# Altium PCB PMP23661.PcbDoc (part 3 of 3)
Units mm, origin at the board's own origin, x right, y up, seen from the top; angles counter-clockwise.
Board outline 209 x 127 mm, 4 copper layers (Top Layer, Layer 1, Layer 2, Bottom Layer), stack 1.787 mm thick; 235 components, 114 nets, 814 pads, 405 vias.
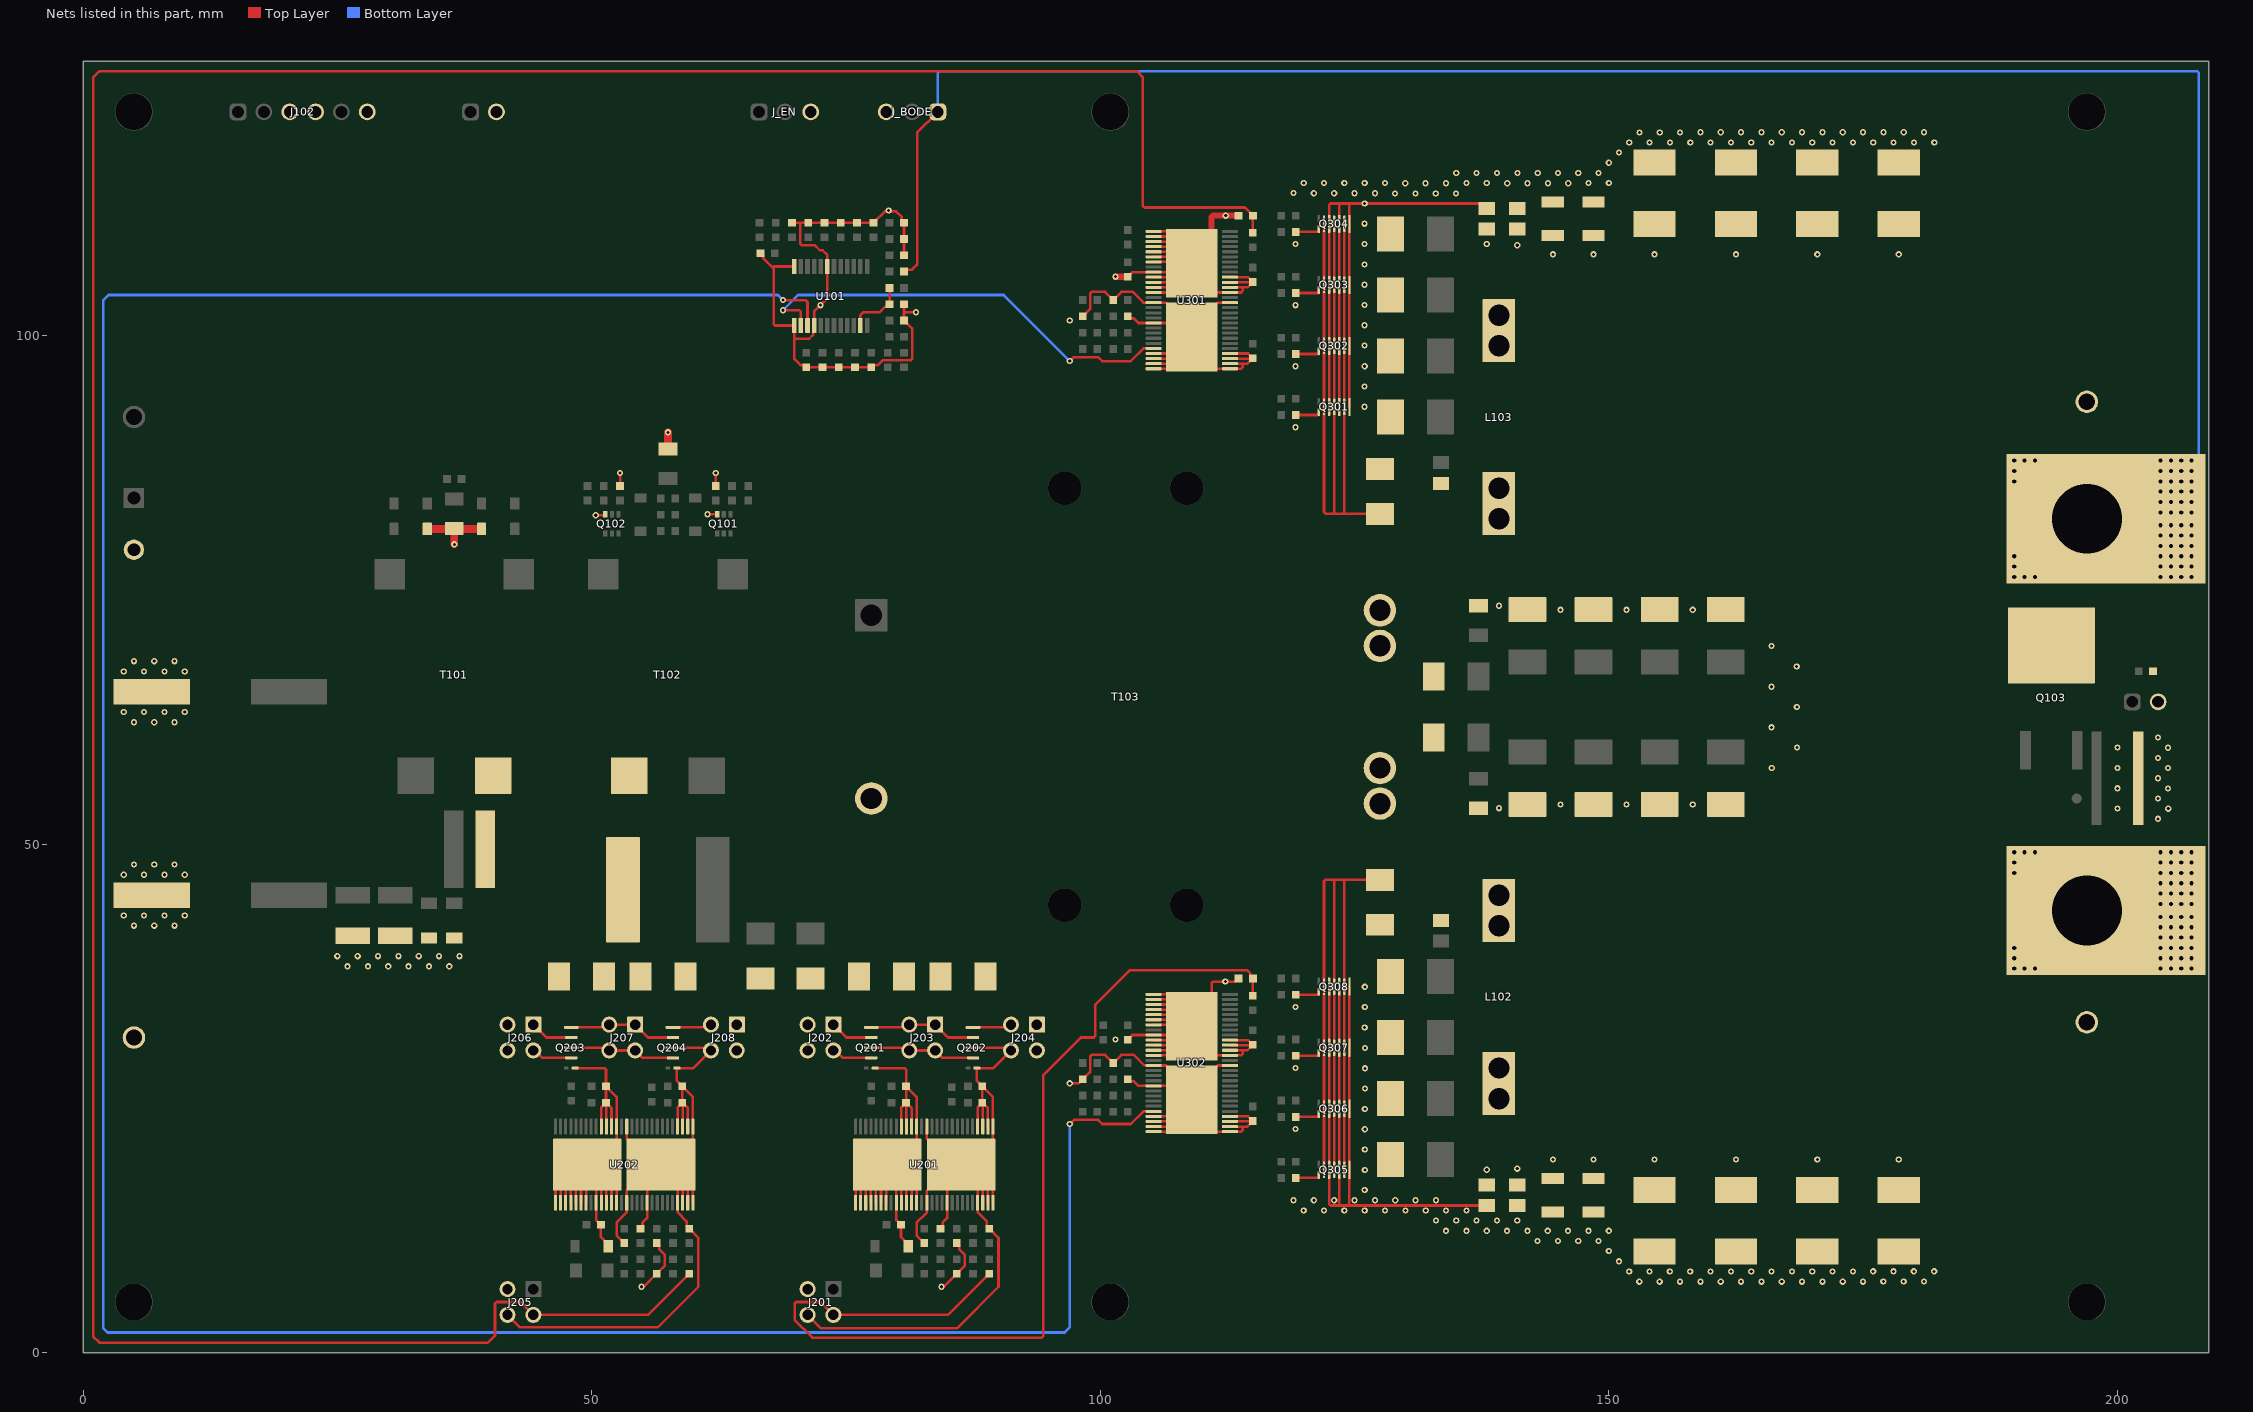
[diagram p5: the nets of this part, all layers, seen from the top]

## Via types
v1: diameter 0.61, hole 0.305, Top Layer to Bottom Layer, 289 vias
v2: diameter 0.813, hole 0.406, Top Layer to Bottom Layer, 116 vias

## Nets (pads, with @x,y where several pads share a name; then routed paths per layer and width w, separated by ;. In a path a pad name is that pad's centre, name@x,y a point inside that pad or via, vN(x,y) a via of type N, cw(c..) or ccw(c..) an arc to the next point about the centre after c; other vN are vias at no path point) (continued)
PGND: C101.2 C102.2 C103.2 C105.2 C107.2 C108.2 C201.2 C202.2 C203.1 C206.1 C207.1 C208.2 C209.1 C212.1 C303.1 C304.1 C310.1 C311.1 D106.2 D108.2 D111.2 J101.2 J102.3 J102.4 J102.6 J201.2 J201.4 J204.1 J204.2 J204.3 J204.4 J205.2 J205.4 J208.1 J208.2 J208.3 J208.4 Q202.2 Q202.4 Q202.6 Q204.2 Q204.4 Q204.6 R205.2 R206.2 R211.2 R216.2 R217.2 R222.2 R313.2 R338.2 TP102.1 U201.15 U201.19 U201.25 U201.26 U201.27 U201.28 U201.29 U201.30 U201.31 U201.32 U201.42 U201.58 U202.15 U202.19 U202.25 U202.26 U202.27 U202.28 U202.29 U202.30 U202.31 U202.32 U202.42 U202.58 U301.1 U301.2 U301.3 U301.4 U301.5 U301.6 U301.7 U301.9 U301.10 U301.11 U301.12 U301.13 U301.44 U301.45 U301.46 U301.47 U301.57 U302.1 U302.2 U302.3 U302.4 U302.5 U302.6 U302.7 U302.9 U302.10 U302.11 U302.12 U302.13 U302.44 U302.45 U302.46 U302.47 U302.57 | length 277
  Top Layer w0.254: J205.4@41.73,3.73 42.96,2.5 56.5,2.5 60.5,6.5 60.5,11.311 C207.1@59.6,12.211 59.346,12.465 59.346,12.936 58.455,13.828 58.455,14.745 U202.25@58.45,14.75 58.45,16.077 57.977,16.55 U202.58@57.6,16.55 ; J205.2@41.73,6.27 J205.2@41.982,6.018 ; C209.1@53.2,10.789 52.45,11.539 52.45,12.804 53.45,13.804 U202.15@53.45,14.75 53.45,15.95 54.05,16.55 U202.58@54.3,16.55 ; U202.42@53.45,22.25 53.45,21.05 54.05,20.45 U202.58@54.3,20.45 ; C208.2@54.8,12.211 55.002,12.413 55.002,12.802 55.45,13.25 U202.19@55.45,14.75 55.45,16.5 U202.58@55.4,16.55 ; v1(54.9,6.5) 54.968,6.568 55.179,6.568 R216.2@56.4,7.789 57.2,8.589 57.2,9.636 56.654,10.182 56.654,10.535 R217.2@56.4,10.789 ; Q204.4@58,30 61.104,30 61.374,29.73 J208.4@61.73,29.73 60,28 Q204.2@58.375,28 58.375,26.736 R222.2@58.911,26.2 ; Q204.6@58,32 61.104,32 61.374,32.27 J208.2@61.73,32.27 ; U202.32@58.45,22.25 58.45,24.139 C212.1@58.911,24.6 ; U202.58@58.7,16.55 58.95,16.3 U202.26@58.95,14.75 ; U202.58@58.7,17.85 59.45,17.1 U202.27@59.45,14.75 ; U202.31@58.95,22.25 58.95,24.561 C212.1@58.911,24.6 ; U202.30@59.45,22.25 59.45,24.061 C212.1@58.911,24.6 ; U202.58@59.8,16.55 59.95,16.4 U202.28@59.95,14.75 ; U202.58@59.8,20.45 59.95,20.6 U202.29@59.95,22.25 59.95,25.161 R222.2@58.911,26.2 ; J201.4@71.23,3.73 72.56,2.4 85.9,2.4 90,6.5 90,11.311 ; C203.1@82.7,10.789 81.95,11.539 81.95,12.804 82.95,13.804 U201.15@82.95,14.75 82.95,15.95 83.55,16.55 U201.58@83.8,16.55 ; U201.42@82.95,22.25 82.95,21.05 83.55,20.45 U201.58@83.8,20.45 ; C202.2@84.3,12.211 84.502,12.413 84.502,12.802 84.95,13.25 U201.19@84.95,14.75 84.95,16.5 U201.58@84.9,16.55 ; v1(84.4,6.5) 84.468,6.568 84.679,6.568 R205.2@85.9,7.789 86.7,8.589 86.7,9.636 86.154,10.182 86.154,10.535 R206.2@85.9,10.789 ; U201.58@87.1,16.55 87.477,16.55 87.95,16.077 U201.25@87.95,14.75 87.955,14.745 87.955,13.828 88.846,12.936 88.846,12.465 C201.2@89.1,12.211 ; Q202.4@87.5,30 90.604,30 90.874,29.73 J204.4@91.23,29.73 89.5,28 Q202.2@87.875,28 87.875,26.736 R211.2@88.411,26.2 ; Q202.6@87.5,32 90.604,32 90.874,32.27 J204.2@91.23,32.27 ; U201.32@87.95,22.25 87.95,24.139 C206.1@88.411,24.6 ; U201.58@88.2,16.55 88.45,16.3 U201.26@88.45,14.75 ; U201.58@88.2,17.85 88.95,17.1 U201.27@88.95,14.75 ; U201.31@88.45,22.25 88.45,24.561 C206.1@88.411,24.6 ; U201.30@88.95,22.25 88.95,24.061 C206.1@88.411,24.6 ; U201.58@89.3,16.55 89.45,16.4 U201.28@89.45,14.75 ; U201.58@89.3,20.45 89.45,20.6 U201.29@89.45,22.25 89.45,25.161 R211.2@88.411,26.2 ; C310.1@102.7,30.789 103.161,31.25 U302.9@105.25,31.25 107.8,31.25 108.35,31.8 107.9,32.25 U302.7@105.25,32.25 ; C303.1@102.7,105.789 103.161,106.25 U301.9@105.25,106.25 107.8,106.25 108.35,106.8 107.9,107.25 U301.7@105.25,107.25 ; U302.13@105.25,29.25 108,29.25 U302.57@108.35,29.6 ; U302.12@105.25,29.75 U302.57@107.05,29.75 ; U302.11@105.25,30.25 U302.57@107.7,30.25 ; U302.10@105.25,30.75 U302.57@107.05,30.75 ; U302.6@105.25,32.75 U302.57@107.05,32.75 ; U302.5@105.25,33.25 107.6,33.25 107.975,33.625 107.85,33.75 U302.4@105.25,33.75 ; U302.3@105.25,34.25 108.1,34.25 107.6,34.75 U302.2@105.25,34.75 ; U302.1@105.25,35.25 U302.57@107.05,35.25 ; U301.13@105.25,104.25 108,104.25 U301.57@108.35,104.6 ; U301.12@105.25,104.75 U301.57@107.05,104.75 ; U301.11@105.25,105.25 U301.57@107.7,105.25 ; U301.10@105.25,105.75 U301.57@107.05,105.75 ; U301.6@105.25,107.75 U301.57@107.05,107.75 ; U301.5@105.25,108.25 107.6,108.25 107.975,108.625 107.85,108.75 U301.4@105.25,108.75 ; U301.3@105.25,109.25 108.1,109.25 107.6,109.75 U301.2@105.25,109.75 ; U301.1@105.25,110.25 U301.57@107.05,110.25 ; U302.57@110.95,29.6 111.3,29.25 U302.44@112.75,29.25 113.851,29.25 114,29.399 114,29.75 ; U302.57@110.95,35.1 110.95,36.351 111.099,36.5 113.186,36.5 113.232,36.546 113.335,36.546 R338.2@113.589,36.8 ; U301.57@110.95,104.6 111.3,104.25 U301.44@112.75,104.25 113.851,104.25 114,104.399 114,104.75 ; U302.45@112.75,29.75 114,29.75 ; U302.46@112.75,30.25 114.961,30.25 C311.1@115,30.289 ; U302.47@112.75,30.75 114.539,30.75 C311.1@115,30.289 ; U301.45@112.75,104.75 114,104.75 ; U301.46@112.75,105.25 114.961,105.25 C304.1@115,105.289 ; U301.47@112.75,105.75 114.539,105.75 C304.1@115,105.289 ; C212.1@58.911,24.6 R222.2@58.911,26.2 ; C206.1@88.411,24.6 R211.2@88.411,26.2 ; C201.2@89.1,12.211 90,11.311 ; C201.2@89.1,12.211 90,11.311 ; 114,29.75 114.461,29.75 C311.1@115,30.289 ; 114,104.75 114.461,104.75 C304.1@115,105.289
  Top Layer w0.6: v1(101.5,105.8) 101.502,105.798 102.691,105.798 C303.1@102.7,105.789 ; U301.57@110.95,110.1 110.95,111.651 111.099,111.8 v1(112.344,111.8) R313.2@113.589,111.8
  other v1: 101.5,30.8 112.3,36.5 26,38 28,38 30,38 32,38 34,38 36,38 25,39 27,39 29,39 31,39 33,39 35,39 37,39 5,42 7,42 9,42 4,43 6,43 8,43 10,43 4,47 6,47 8,47 10,47 5,48 7,48 9,48 5,62 7,62 9,62 4,63 6,63 8,63 10,63 4,67 6,67 8,67 10,67 5,68 7,68 9,68
PRIswA: C210.1 C211.1 D105.2 D106.1 D204.2 J207.1 J207.2 J207.3 J207.4 L101.1 Q203.2 Q203.4 Q203.6 Q204.3 Q204.5 R221.2 T102.1 U202.1 U202.2 U202.3 U202.4 U202.5 U202.6 U202.7 U202.9 U202.10 U202.11 U202.12 U202.13 U202.44 U202.45 U202.46 U202.47 U202.57 | length 80.7
  Top Layer w0.254: U202.1@46.45,14.75 46.45,16.4 U202.57@46.6,16.55 ; U202.2@46.95,14.75 U202.57@46.95,17.5 ; U202.3@47.45,14.75 47.45,17.6 U202.57@47.7,17.85 ; U202.4@47.95,14.75 U202.57@47.95,17.6 ; Q203.4@48,30 J207.4@51.73,30 ; Q203.6@48,32 52,32 J207.2@51.73,32.27 J207.1@54.27,32.27 55.54,31 Q204.5@58,31 ; Q203.2@48.375,28 51.262,28 51.411,27.851 R221.2@51.411,26.2 ; U202.5@48.45,14.75 48.45,17.5 U202.57@48.8,17.85 ; U202.57@48.8,16.55 48.95,16.4 U202.6@48.95,14.75 ; U202.7@49.45,14.75 49.45,18.375 U202.57@49.575,18.5 ; U202.10@50.95,14.75 U202.57@50.95,16.55 ; U202.47@50.95,22.25 50.95,24.139 C211.1@51.411,24.6 ; U202.57@51,17.85 50.45,17.3 U202.9@50.45,14.75 50.45,13.061 C210.1@50.911,12.6 50.911,11.379 51.637,10.653 D204.2@51.637,10.5 ; U202.57@51,19.15 51.45,18.7 U202.11@51.45,14.75 ; U202.46@51.45,22.25 C211.1@51.45,24.561 ; J207.4@51.73,29.73 J207.3@54.27,29.73 55,29 Q204.3@58,29 ; U202.12@51.95,14.75 U202.57@51.95,16.55 ; U202.45@51.95,22.25 51.95,24.061 C211.1@51.411,24.6 ; U202.57@52.1,17.85 52.45,17.5 U202.13@52.45,14.75 ; U202.57@52.1,20.45 52.45,20.8 U202.44@52.45,22.25 52.45,25.161 R221.2@51.411,26.2 ; C211.1@51.411,24.6 R221.2@51.411,26.2
PRIswB: C204.1 C205.1 D107.2 D108.1 D202.2 J203.1 J203.2 J203.3 J203.4 Q201.2 Q201.4 Q201.6 Q202.3 Q202.5 R210.2 T103.2 U201.1 U201.2 U201.3 U201.4 U201.5 U201.6 U201.7 U201.9 U201.10 U201.11 U201.12 U201.13 U201.44 U201.45 U201.46 U201.47 U201.57 | length 80.7
  Top Layer w0.254: U201.1@75.95,14.75 75.95,16.4 U201.57@76.1,16.55 ; U201.2@76.45,14.75 U201.57@76.45,17.5 ; U201.3@76.95,14.75 76.95,17.6 U201.57@77.2,17.85 ; U201.4@77.45,14.75 U201.57@77.45,17.6 ; Q201.4@77.5,30 J203.4@81.23,30 ; Q201.6@77.5,32 81.5,32 J203.2@81.23,32.27 J203.1@83.77,32.27 85.04,31 Q202.5@87.5,31 ; Q201.2@77.875,28 80.762,28 80.911,27.851 R210.2@80.911,26.2 ; U201.5@77.95,14.75 77.95,17.5 U201.57@78.3,17.85 ; U201.57@78.3,16.55 78.45,16.4 U201.6@78.45,14.75 ; U201.7@78.95,14.75 78.95,18.375 U201.57@79.075,18.5 ; U201.10@80.45,14.75 U201.57@80.45,16.55 ; U201.47@80.45,22.25 80.45,24.139 C205.1@80.911,24.6 ; U201.57@80.5,17.85 79.95,17.3 U201.9@79.95,14.75 79.95,13.061 C204.1@80.411,12.6 80.411,11.379 81.137,10.652 D202.2@81.137,10.5 ; U201.57@80.5,19.15 80.95,18.7 U201.11@80.95,14.75 ; U201.46@80.95,22.25 80.95,24.561 C205.1@80.911,24.6 ; J203.4@81.23,29.73 J203.3@83.77,29.73 84.5,29 Q202.3@87.5,29 ; U201.12@81.45,14.75 U201.57@81.45,16.55 ; U201.45@81.45,22.25 81.45,24.061 C205.1@80.911,24.6 ; U201.57@81.6,17.85 81.95,17.5 U201.13@81.95,14.75 ; U201.57@81.6,20.45 81.95,20.8 U201.44@81.95,22.25 81.95,25.161 R210.2@80.911,26.2 ; C205.1@80.911,24.6 R210.2@80.911,26.2
PWMA: J205.3 R212.2 R312.1 R313.1 | length 317.6
  Top Layer w0.254: R212.2@59.6,7.789 55.541,3.73 J205.3@44.27,3.73 43,5 40.649,5 40.5,4.851 40.5,1.7 39.8,1 1.6,1 1,1.6 1,125.4 1.6,126 103.6,126 104.2,125.4 104.2,112.749 104.349,112.6 114.211,112.6 114.757,112.054 R313.1@115.011,111.8 115,111.789 R312.1@115,110.111
PWMB: J201.3 R201.2 R337.1 R338.1 | length 102.7
  Top Layer w0.254: R201.2@89.1,7.789 85.041,3.73 J201.3@73.77,3.73 72.5,5 70.109,5 69.96,4.851 69.96,3.24 71.7,1.5 94.251,1.5 94.4,1.649 94.4,27.3 98.1,31 99.351,31 99.5,31.149 99.5,34.211 102.889,37.6 114.469,37.6 114.757,37.312 114.757,37.054 R338.1@115.011,36.8 115,36.789 R337.1@115,35.111
SECswA: C314.1 D113.1 D302.2 L102.1 Q305.3 Q305.5 Q305.7 Q306.3 Q306.5 Q306.7 Q307.3 Q307.5 Q307.7 Q308.3 Q308.5 Q308.7 T103.3 | length 90.9
  Top Layer w0.254: Q305.3@122,18 Q306.3@122,24 Q307.3@122,30 Q308.3@122,36 122,46.361 122.149,46.51 123,46.51 ; Q305.5@123,18 Q306.5@123,24 Q307.5@123,30 Q308.5@123,36 123,46.51 ; Q305.7@124,18 124,46.51 ; D113.1@127.5,46.51 124,46.51 ; 123,46.51 124,46.51
SECswB: C307.1 D114.1 D301.2 L103.2 Q301.3 Q301.5 Q301.7 Q302.3 Q302.5 Q302.7 Q303.3 Q303.5 Q303.7 Q304.3 Q304.5 Q304.7 T103.4 | length 90.9
  Top Layer w0.254: Q304.3@122,111 Q303.3@122,105 Q302.3@122,99 Q301.3@122,93 122,82.69 122.2,82.49 123,82.49 ; Q304.5@123,111 Q303.5@123,105 Q302.5@123,99 Q301.5@123,93 123,82.49 ; Q304.7@124,111 Q303.7@124,105 Q302.7@124,99 Q301.7@124,93 124,82.49 ; D114.1@127.5,82.49 124,82.49 ; 123,82.49 124,82.49
SGND: C104.2 C106.1 C109.1 C110.2 C111.1 C112.2 C113.2 C114.2 C115.2 C116.2 C117.2 C118.2 C119.2 C120.2 C121.2 C122.2 C123.2 C124.2 C125.2 C126.2 C127.2 C128.2 C129.2 C130.2 C301.2 C302.1 C306.1 C308.2 C309.1 C313.1 D102.2 D104.2 D113.2 D114.2 J103.2 J105.1 J106.2 J_BODE.3 J_EN.3 Q101.3 Q102.3 Q301.2 Q301.4 Q301.6 Q301.8 Q302.2 Q302.4 Q302.6 Q302.8 Q303.2 Q303.4 Q303.6 Q303.8 Q304.2 Q304.4 Q304.6 Q304.8 Q305.2 Q305.4 Q305.6 Q305.8 Q306.2 Q306.4 Q306.6 Q306.8 Q307.2 Q307.4 Q307.6 Q307.8 Q308.2 Q308.4 Q308.6 Q308.8 R103.2 R104.1 R107.2 R108.1 R111.1 R112.1 R113.1 R117.1 R120.1 R121.1 R122.1 R124.2 R129.1 R130.1 R131.1 R303.2 R314.1 R319.1 R320.2 R321.2 R322.2 R323.2 R324.1 R325.1 R328.2 R339.1 R344.1 R345.2 R346.2 R347.2 R348.2 R349.1 R350.1 TP105.1 U101.7 U101.12 U101.13 U101.16 U301.15 U301.19 U301.25 U301.26 U301.27 U301.28 U301.29 U301.30 U301.31 U301.32 U301.42 U301.58 U302.15 U302.19 U302.25 U302.26 U302.27 U302.28 U302.29 U302.30 U302.31 U302.32 U302.42 U302.58 | length 341.4
  Top Layer w0.254: v1(50.4,82.35) Q102.3@51.35,82.35 ; R120.1@52.8,85.211 v1(52.8,86.5) ; v1(61.4,82.45) Q101.3@62.35,82.45 ; R112.1@62.2,85.211 v1(62.2,86.5) ; C104.2@66.589,108.1 66.843,107.846 66.843,107.657 67.889,106.611 ; R103.2@69.7,111.111 70.5,111.111 ; U101.12@69.925,106.8 67.889,106.8 67.889,106.611 ; R129.1@80.711,103.1 80.711,102.3 ; C110.2@80.711,107.9 R121.1@80.711,109.5 R111.1@80.711,111.1 80.493,111.319 80.493,111.674 79.935,112.232 79.268,112.232 v1(79.2,112.3) 79.132,112.232 78.821,112.232 R108.1@77.7,111.111 R107.2@74.5,111.111 70.5,111.111 ; v1(81.9,102.3) 80.711,102.3 ; v1(97,26.5) 97.889,26.5 99,27.611 99,29.151 99.149,29.3 100.489,29.3 C309.1@101.289,28.5 102.089,29.3 103.3,29.3 104.327,28.273 105.227,28.273 U302.15@105.25,28.25 106.45,28.25 107.3,27.4 U302.58@108.35,27.4 ; R303.2@98.289,101.9 99,102.611 99,104.151 99.149,104.3 100.489,104.3 C302.1@101.289,103.5 102.089,104.3 103.2,104.3 104.25,103.25 106.45,103.25 107.3,102.4 U301.58@108.35,102.4 ; C308.2@102.711,26.9 102.913,26.698 103.302,26.698 103.75,26.25 U302.19@105.25,26.25 107,26.25 U302.58@107.05,26.3 ; C301.2@102.711,101.9 102.913,101.698 103.302,101.698 103.75,101.25 U301.19@105.25,101.25 107,101.25 U301.58@107.05,101.3 ; U302.28@105.25,21.75 106.9,21.75 U302.58@107.05,21.9 ; U302.27@105.25,22.25 U302.58@108,22.25 ; U302.26@105.25,22.75 108.1,22.75 U302.58@108.35,23 ; U302.25@105.25,23.25 U302.58@108.1,23.25 ; U301.28@105.25,96.75 106.9,96.75 U301.58@107.05,96.9 ; U301.27@105.25,97.25 U301.58@108,97.25 ; U301.26@105.25,97.75 108.1,97.75 U301.58@108.35,98 ; U301.25@105.25,98.25 U301.58@108.1,98.25 ; U302.58@109.65,27.4 110.7,27.4 111.55,28.25 U302.42@112.75,28.25 ; U301.58@109.65,102.4 110.7,102.4 111.55,103.25 U301.42@112.75,103.25 ; U302.58@110.95,21.9 111.1,21.75 U302.29@112.75,21.75 113.851,21.75 114,21.899 114,22.25 ; U301.58@110.95,96.9 111.1,96.75 U301.29@112.75,96.75 113.851,96.75 114,96.899 114,97.25 ; U302.30@112.75,22.25 114,22.25 ; U302.31@112.75,22.75 114.961,22.75 114.961,22.828 114.539,23.25 U302.32@112.75,23.25 ; U301.30@112.75,97.25 114,97.25 ; U301.31@112.75,97.75 114.961,97.75 114.961,97.828 114.539,98.25 U301.32@112.75,98.25 ; C313.1@115,22.789 114.461,22.25 114,22.25 ; C306.1@115,97.789 114.461,97.25 114,97.25 ; R345.2@119.211,17.2 121.451,17.2 121.5,17.249 Q305.2@121.5,17.488 ; R346.2@119.211,23.2 121.451,23.2 121.5,23.249 Q306.2@121.5,23.487 ; R347.2@119.211,29.2 121.451,29.2 121.5,29.249 Q307.2@121.5,29.487 ; R348.2@119.211,35.2 121.451,35.2 121.5,35.249 Q308.2@121.5,35.487 ; R320.2@119.211,92.2 121.451,92.2 121.5,92.249 Q301.2@121.5,92.487 ; R321.2@119.211,98.2 121.451,98.2 121.5,98.249 Q302.2@121.5,98.487 ; R322.2@119.211,104.2 121.451,104.2 121.5,104.249 Q303.2@121.5,104.487 ; R323.2@119.211,110.2 121.451,110.2 121.5,110.249 Q304.2@121.5,110.487 ; Q308.4@122.5,36 Q307.4@122.5,30 Q306.4@122.5,24 Q305.4@122.5,18 122.5,14.633 122.649,14.484 123.5,14.484 ; Q301.4@122.5,93 Q302.4@122.5,99 Q303.4@122.5,105 Q304.4@122.5,111 122.5,112.851 122.649,113 123.5,113 ; Q308.6@123.5,36 Q307.6@123.5,30 Q306.6@123.5,24 Q305.6@123.5,18 123.5,14.484 ; Q301.6@123.5,93 Q302.6@123.5,99 Q303.6@123.5,105 Q304.6@123.5,111 123.5,113 ; Q308.8@124.5,36 124.5,14.484 ; Q301.8@124.5,93 Q304.8@124.5,111 124.5,113 ; C123.2@138,14.484 124.5,14.484 ; C115.2@138,112.516 137.516,113 124.5,113 ; 67.889,106.611 67.889,101.149 68.038,101 U101.13@69.925,101 69.925,99.7 ; 69.925,99.7 69.925,97.708 70.526,97.107 70.881,97.107 C106.1@71.1,96.889 C112.2@72.7,96.889 R124.2@74.3,96.889 C111.1@75.9,96.889 C114.2@77.5,96.889 77.69,97.078 78.103,97.078 78.625,97.6 81.351,97.6 81.5,97.749 81.5,100.711 C113.2@80.711,101.5 80.711,102.3 ; 69.925,99.7 71.394,99.7 71.796,100.102 71.796,100.921 U101.16@71.875,101 71.875,102.375 v1(72.5,103) 73.175,103.675 U101.7@73.175,106.8 73.175,107.925 72.7,108.4 72.425,108.4 71.925,108.9 70.649,108.9 70.5,109.049 70.5,111.111 ; 123.5,14.484 124.5,14.484 ; 123.5,113 124.5,113
  Top Layer w0.762: D104.2@33.835,81 D102.2@39.165,81 ; v1(36.5,79.491) R104.1@36.5,81.05 ; R122.1@57.5,88.85 v1(57.5,90.5)
  other v1: 153,7 155,7 157,7 159,7 161,7 163,7 165,7 167,7 169,7 171,7 173,7 175,7 176.988,7.015 178.988,7.015 180.988,7.015 152,8 154,8 156,8 158,8 160,8 162,8 164,8 166,8 168,8 170,8 172,8 174,8 175.988,8.015 177.988,8.015 179.988,8.015 181.988,8.015 151,9 150,10 143,11 145,11 147,11 149,11 134,12 136,12 138,12 140,12 142,12 144,12 146,12 148,12 150,12 133,13 135,13 137,13 139,13 141,13 120,14 122,14 124,14 126,14 128,14 130,14 132,14 134,14 136,14 119,15 121,15 123,15 125,15 127,15 129,15 131,15 133,15 126,16 126.015,17.988 126.015,19.988 119.211,22 126.015,21.988 126.015,23.988 126.029,25.976 126.029,27.976 119.211,28 126.029,29.976 126,32 126.015,33.988 119.211,34 126.015,35.988 204,52.5 205,53.5 200.015,53.512 203.985,54.488 200,55.5 204.985,55.488 203.985,56.488 204.985,57.488 200,57.5 203.985,58.488 204.985,59.488 200,59.5 203.985,60.488 119.211,91 125.985,93.012 125.985,95.012 119.211,97 126,97 125.971,99.024 125.971,101.024 97,101.5 119.211,103 125.971,103.024 125.985,105.012 125.985,107.012 119.211,109 125.985,109.012 125.985,111.012 126,113 121,114 123,114 125,114 127,114 128.988,113.985 130.988,113.985 132.988,113.985 134.988,113.985 119.012,114.015 129.988,114.985 131.988,114.985 133.988,114.985 140.012,114.985 142.012,114.985 144.012,114.985 146.012,114.985 120.012,115.015 122,115 124,115 126,115 128,115 136,115 138,115 148,115 150,115 141.012,115.985 143.012,115.985 145.012,115.985 135,116 137,116 139,116 147,116 149,116 150,117 151,118 152.012,118.985 154.012,118.985 156.012,118.985 158.012,118.985 160,119 162,119 164,119 166,119 168,119 170,119 172,119 174,119 176,119 178,119 180,119 182,119 153.012,119.985 155.012,119.985 157.012,119.985 159,120 161,120 163,120 165,120 167,120 169,120 171,120 173,120 175,120 177,120 179,120 181,120
  other v2: 189.856,37.785 190.872,37.785 191.888,37.785 204.239,37.785 205.255,37.785 206.271,37.785 207.287,37.785 189.856,38.801 204.239,38.801 205.255,38.801 206.271,38.801 207.287,38.801 189.856,39.817 204.239,39.817 205.255,39.817 206.271,39.817 207.287,39.817 204.239,40.833 205.255,40.833 206.271,40.833 207.287,40.833 204.239,41.849 205.255,41.849 206.271,41.849 207.287,41.849 204.239,42.865 205.255,42.865 206.271,42.865 207.287,42.865 204.239,44.135 205.255,44.135 206.271,44.135 207.287,44.135 204.239,45.151 205.255,45.151 206.271,45.151 207.287,45.151 204.239,46.167 205.255,46.167 206.271,46.167 207.287,46.167 189.856,47.183 204.239,47.183 205.255,47.183 206.271,47.183 207.287,47.183 189.856,48.199 204.239,48.199 205.255,48.199 206.271,48.199 207.287,48.199 189.856,49.215 190.872,49.215 191.888,49.215 204.239,49.215 205.255,49.215 206.271,49.215 207.287,49.215
SRA: U101.15 U302.24 | length 297.6
  Top Layer w0.254: v1(68.8,103.5) 71.025,103.5 71.225,103.3 U101.15@71.225,101 ; v1(97,22.5) 97.027,22.5 97.427,22.9 99.8,22.9 100.2,22.5 103,22.5 104.248,23.748 105.248,23.748 U302.24@105.25,23.75
  Bottom Layer w0.254: v1(68.8,103.5) 68.3,104 2.5,104 2,103.5 2,2.4 2.4,2 96.5,2 97,2.5 v1(97,22.5)
SRB: U101.14 U301.24 | length 43.8
  Top Layer w0.254: v1(68.8,102.5) 70.426,102.5 70.575,102.351 U101.14@70.575,101 ; v1(97,97.5) 97.027,97.5 97.427,97.9 99.8,97.9 100.2,97.5 103,97.5 104.248,98.748 105.248,98.748 U301.24@105.25,98.75
  Bottom Layer w0.254: v1(68.8,102.5) 70.3,104 90.5,104 v1(97,97.5)
VIN: D105.1 D107.1 D110.1 J202.1 J202.2 J202.3 J202.4 J206.1 J206.2 J206.3 J206.4 Q201.3 Q201.5 Q203.3 Q203.5 R106.1 T101.2 | length 16.6
  Top Layer w0.254: J206.3@44.27,29.73 44.459,29.73 45.189,29 Q203.3@48,29 ; J206.1@44.27,32.27 45.54,31 Q203.5@48,31 ; J202.3@73.77,29.73 73.959,29.73 74.689,29 Q201.3@77.5,29 ; J202.1@73.77,32.27 75.04,31 Q201.5@77.5,31
VOUT: C115.1 C116.1 C117.1 C118.1 C119.1 C120.1 C121.1 C122.1 C123.1 C124.1 C125.1 C126.1 C127.1 C128.1 C129.1 C130.1 C305.2 C312.2 J104.1 J_BODE.1 L102.2 L103.1 Q103.4 R127.2 R307.2 R308.2 R309.2 R311.2 R332.2 R333.2 R334.2 R336.2 TP104.1 | length 206.7
  Top Layer w0.254: R127.2@80.711,106.3 80.911,106.5 81.5,106.5 82,107 82,119.96 J_BODE.1@84.04,122
  Bottom Layer w0.254: J_BODE.1@84.04,122 84.04,125.851 84.189,126 207.851,126 208,125.851 J104.1@208,85.7 ; J104.1@197,82 J104.1@201.572,82 ; v2(207.287,86.699) v2(206.271,85.683) v2(205.255,84.667) v2(204.239,83.651) 202.588,82 J104.1@201.572,82 ; J104.1@208,88.223 207.492,87.715 v2(207.287,87.715) J104.1@201.572,82
  other v1: 138,18 141,18.107 144.5,19 148.5,19 154.5,19 162.5,19 170.5,19 178.5,19 139.2,53.55 145.25,53.9 151.75,53.9 158.25,53.9 166.015,57.512 168.5,59.5 166,61.5 168.485,63.488 165.985,65.488 168.471,67.476 165.985,69.488 145.25,73.05 151.75,73.05 158.25,73.05 139.2,73.45 144.5,108 148.5,108 154.5,108 162.5,108 170.5,108 178.5,108 141,108.893 138,109
  other v2: 189.856,76.285 190.872,76.285 191.888,76.285 204.239,76.285 205.255,76.285 206.271,76.285 207.287,76.285 189.856,77.301 204.239,77.301 205.255,77.301 206.271,77.301 207.287,77.301 189.856,78.317 204.239,78.317 205.255,78.317 206.271,78.317 207.287,78.317 204.239,79.333 205.255,79.333 206.271,79.333 207.287,79.333 204.239,80.349 205.255,80.349 206.271,80.349 207.287,80.349 204.239,81.365 205.255,81.365 206.271,81.365 207.287,81.365 204.239,82.635 205.255,82.635 206.271,82.635 207.287,82.635 205.255,83.651 206.271,83.651 207.287,83.651 204.239,84.667 206.271,84.667 207.287,84.667 189.856,85.683 204.239,85.683 205.255,85.683 207.287,85.683 189.856,86.699 204.239,86.699 205.255,86.699 206.271,86.699 189.856,87.715 190.872,87.715 191.888,87.715 204.239,87.715 205.255,87.715 206.271,87.715
VSENSE: R128.1 R129.2 U101.23 | length 5.9
  Top Layer w0.254: U101.23@76.425,101 76.425,102.025 76.7,102.3 78.3,102.3 78.846,102.846 79.035,102.846 R129.2@79.289,103.1 R128.1@79.289,104.7
pads on no net: H301.0 H301.MH H302.0 H302.MH H303.0 H303.MH H304.0 H304.MH H305.0 H305.MH H306.0 H306.MH T103. U201.14 U201.16 U201.43 U202.14 U202.16 U202.43 U301.14 U301.16 U301.43 U302.14 U302.16 U302.43

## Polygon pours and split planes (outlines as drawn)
SGND on Top Layer "TOP_LAYER_SGND_P020" (solid, remove dead copper, pour order 20): 38.6,127 209,127 209,0 95.5,0 95.5,26 98.5,29 103,29 104,28 114.5,28 116,29.5 116,40 122,40 122,89 74,89 74,78.6 30.565,78.6 30.565,82.45 38.6,82.45
HV on Top Layer "TOP_LAYER_HV_P019" (solid, remove dead copper, pour order 19): 0,127 33,127 33,92 27,86 27,70.8 37.8,60 38.3,60 38.3,42.5 0,42.5
PGND on Top Layer "TOP_LAYER_PGND_P013" (solid, remove dead copper, pour order 13): 0,81 0,0 95,0 95,27.1 98.3,30.4 103.5,30.4 104.9,29 114,29 115,30 115,40 38,40 38,42.5 11,42.5 11,76 6,81
VIN on Top Layer "TOP_LAYER_VIN_P012" (solid, remove dead copper, pour order 12): 49.5,60 38.3,60 38.3,23 49.5,23
VIN on Top Layer "TOP_LAYER_VIN_P011" (solid, remove dead copper, pour order 11): 79,39.5 69.2,39.5 69.2,23 79,23
PRIswA on Top Layer "TOP_LAYER_PRISWA_P010" (solid, remove dead copper, pour order 10): 49.5,60 49.5,36 47.5,34 47.5,23.5 58.5,23.5 58.5,32 56.7,32 56.7,59 55.7,60
PRIswB on Top Layer "TOP_LAYER_PRISWB_P009" (solid, remove dead copper, pour order 9): 76,57 75,56 75,40 79,40 79,36 77,34 77,23.5 88,23.5 88,32 86.2,32 86.2,49.8 79,57
NetD110_2 on Top Layer "TOP_LAYER_NETD110_2_P008" (solid, remove dead copper, pour order 8): 59,40 59,59 75,75 80,75 80,70 74,64 74,40
VOUT on Top Layer "TOP_LAYER_VOUT_P007" (solid, remove dead copper, pour order 7): 135.5,111.5 150.5,111.5 152,113 209,113 209,67.9 201.46,67.9 201.46,64 199.26,61.8 191.8,61.8 191.8,51.6 188.5,51.6 188.5,21.5 181,14 152,14 150.5,15.5 135.5,15.5
SECswB on Top Layer "TOP_LAYER_SECSWB_P006" (solid, remove dead copper, pour order 6): 135,63.5 121,63.5 121,91.5 125,91.5 125,84 130.7,84 132,85.3 132,87 141,87 141,81 135,75
SECswA on Top Layer "TOP_LAYER_SECSWA_P005" (solid, remove dead copper, pour order 5): 135,63 121,63 121,37.5 125,37.5 125,45 128.2,45 132,41.2 132,40 141,40 141,47 135,53
NetD109_2 on Top Layer "TOP_LAYER_NETD109_2_P001" (solid, remove dead copper, pour order 1): 57.8,84.8 57.8,75 65.4,75 65.4,78.3 61.7,82 61.7,84.8
NetD112_2 on Top Layer "TOP_LAYER_NETD112_2_P000" (solid, remove dead copper, pour order 0): 57.2,84.8 57.2,75 49.6,75 49.6,78.3 53.3,82 53.3,84.8
PGND on Layer 1 "LAYER_1_PGND_P002" (solid, remove dead copper, pour order 2): 115,104 116,105 116,113 115,114 106,114 105,115 105,127 32,127 32,124.4 98.8,124.4 100.6,122.6 100.6,105.4 102,104
PGND on Layer 1 "LAYER_1_PGND_P004" (solid, remove dead copper, pour order 4): 0,127 0,0 95,0 95,27.1 98.3,30.4 103.2,30.4 104.6,29 114,29 115,30 115,40 83,40 83,69 74,69 74,74 27,74 27,86 33,92 33,127
SGND on Layer 1 "LAYER_1_SGND_P003" (solid, remove dead copper, pour order 3): 34,127 209,127 209,0 96,0 96,26.5 98.5,29 103,29 104,28 114.5,28 116,29.5 116,40 121,40 121,89 74,89 74,75 28,75 28,85.5 34,91.5
VOUT on Bottom Layer "BOTTOM_LAYER_VOUT_P014" (solid, remove dead copper, pour order 14): 135.5,111.5 150.5,111.5 152,113 207,113 207,88.3 209,88.3 209,49.5 188.5,49.5 188.5,21.5 181,14 152,14 150.5,15.5 135.5,15.5
SGND on Bottom Layer "BOTTOM_LAYER_SGND_P021" (solid, remove dead copper, pour order 21): 0,127 209,127 209,0 0,0
PGND on Bottom Layer "BOTTOM_LAYER_PGND_P017" (solid, remove dead copper, pour order 17): 3,105 3,3 95,3 95,27.1 98.3,30.4 103.2,30.4 104.6,29 114,29 115,30 115,40 83,40 83,69 74,69 74,74 27,74 27,86 33,92 33,105
VIN on Bottom Layer "BOTTOM_LAYER_VIN_P016" (solid, remove dead copper, pour order 16): 79,39.5 38.5,39.5 38.5,23 79,23
SGND on Layer 2 "LAYER_2_SGND_P018" (solid, remove dead copper, pour order 18): 0,127 209,127 209,0 0,0
PGND on Layer 2 "LAYER_2_PGND_P015" (solid, remove dead copper, pour order 15): 3,101.9 3,3 95,3 95,27.1 98.3,30.4 103.2,30.4 104.6,29 114,29 115,30 115,40 83,40 83,69 74,69 74,74 27,74 27,86 33,92 33,101.9

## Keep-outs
Keep-Out Layer:
  text ".Layer_Name" at 14.656,-21.806 h1.52

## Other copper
Top Layer:
  rectangle net NetQ103_3: 191.7,51.6 198.6,61.3
  region net SGND: 121.55,110.865 120.7,110.865 120.7,110.1 121.55,110.1
  region net SGND: 121.55,104.865 120.7,104.865 120.7,104.1 121.55,104.1
  region net SGND: 121.55,98.865 120.7,98.865 120.7,98.1 121.55,98.1
  region net SGND: 121.55,17.865 120.7,17.865 120.7,16.735 121.55,16.735
  region net SGND: 121.55,23.865 120.7,23.865 120.7,23.1 121.55,23.1
  region net SGND: 121.55,29.865 120.7,29.865 120.7,29.1 121.55,29.1
  region net SGND: 121.55,35.865 120.7,35.865 120.7,35.1 121.55,35.1
  rectangle net SGND: 124.45,16.311 124.9,36.99
  region net SGND: 121.55,92.634 120.545,92.634 120.545,91.979 121.55,91.979
  rectangle net SGND: 124.45,92.018 124.75,112.95
  region net SGND: 111.5,98.3 111.5,98 114.6,98 114.6,98.3
  region net SGND: 104.501,98.3 104.501,98 107.2,98 107.2,98.3
  region net SGND: 104.525,23.3 104.525,23 107.2,23 107.2,23.3
  region net SGND: 111.5,23.3 111.5,23 114.7,23 114.7,23.3
  region net PGND: 110.8,30.8 110.8,30.5 114.566,30.5 114.566,30.8
  region net PGND: 114,29.2 114,29.5 110.8,29.5 110.8,29.2
  region net PGND: 107.2,32.2 107.2,32.5 103.589,32.5 103.589,32.2
  region net PGND: 103.1,31.3 103.1,31 106.5,31 106.5,31.3
  region net PGND: 107.3,29.2 107.3,29.6 104.4,29.6 104.4,29.2
  rectangle net PGND: 58.4,21 58.7,24.2
  rectangle net PGND: 87.9,21 88.2,24.2
  rectangle net PRIswB: 80.5,23.5 80.7,24.2
  rectangle net PRIswA: 51,23.5 51.2,24.2
  region net NetC312_1: 135.6,63.4 135.6,56 164,56 164,63.4
  region net NetC305_1: 135.6,71 135.6,63.6 164,63.6 164,71
  rectangle net NetC307_2: 132,86.8 135,112
  rectangle net NetC314_2: 132,17 135,41.2
  pour cut-out: 104,107.125 98,107.125 98,102.9 104,102.9
  text ".Layer_Name" at 14.656,-21.806 h1.52
Layer 2:
  pour cut-out: 83,40 83,69 74,69 74,89 121,89 121,40
Bottom Layer:
  pour cut-out: 83,40 83,69 74,69 74,89 121,89 121,40
  text ".Layer_Name" at 14.656,-21.806 h1.52

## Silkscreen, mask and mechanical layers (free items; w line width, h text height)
Top Overlay:
  lines w0.152: 11.7,79 13.3,79 ; 12,78.6 13,78.6 ; 12.3,78.2 12.7,78.2 ; 12.5,79 12.5,79.8 ; 20.3,120.3 20.3,119.5 28,119.5 ; 22.9,119.5 22.9,120.3 ; 27.2,118.9 28.8,118.9 ; 27.5,118.5 28.5,118.5 ; 27.8,118.1 28.2,118.1 ; 28,118.9 28,120.3 ; 40.6,118.9 40.6,120.3 ; 46.9,79.7 48.9,79.7 ; 47.9,79.7 47.9,79 57.5,79 57.5,79.9 ; 71.5,119 71.5,120.4 ; 79,119 79,120.4 ; 57.5,79.9 57.7,79.7 57.3,79.7 57.5,79.9 ; 39.8,118.9 41.4,118.9 40.6,118.1 39.8,118.9 ; 70.7,119 71.5,118.2 72.3,119 70.7,119 ; 78.2,119 79,118.2 79.8,119 78.2,119
  text "'.PRJ_Number'.PCB_Rev" at 13,9.052 h3
  text ".Layer_Name" at 14.656,-21.806 h1.52
Bottom Overlay:
  text ".Layer_Name" at 14.656,-21.806 h1.52
Top Paste:
  text ".Layer_Name" at 14.656,-21.806 h1.52
Bottom Paste:
  text ".Layer_Name" at 14.656,-21.806 h1.52
Top Solder:
  text ".Layer_Name" at 14.656,-21.806 h1.52
  text ".Layer_Name" at 14.656,-21.806 h1.52
Bottom Solder:
  text ".Layer_Name" at 14.656,-21.806 h1.52
Drill Guide:
  text ".Layer_Name" at 14.656,-21.806 h1.52
M1 Board Outline:
  the board outline again, w0.254
  text ".Layer_Name" at 14.656,-21.806 h1.52
M2 Board Dimensions:
  rectangle: 0,-6.985 3.175,-3.81
  rectangle: 3.175,-10.16 12.7,-6.985
  lines w0.178: 0,-6.985 25.4,-6.985 ; 3.175,-10.16 3.175,-3.81 ; 6.35,-10.16 6.35,-3.81 ; 12.7,-10.16 12.7,-3.81 ; 19.05,-10.16 19.05,-3.81 ; 0,-10.16 25.4,-10.16 25.4,-3.81 0,-3.81 0,-10.16
  text ".Layer_Name" at 14.656,-21.806 h1.52
M3 3D STEP Top:
  text ".Layer_Name" at 14.656,-21.806 h1.52
M4 3D STEP Bottom:
  text ".Layer_Name" at 14.656,-21.806 h1.52
M5 Assembly Top:
  lines w0.254: -7.417,-23.626 160.223,-23.626 ; -7.417,-18.462 160.274,-18.462 ; -7.417,-13.297 -7.417,-28.791 94.31,-28.791 160.274,-28.791 160.274,-13.297 -7.404,-13.297 -7.404,-28.791 32.614,-28.791 ; 55.194,-28.791 55.194,-13.297 ; 87.376,-18.462 87.376,-13.297 ; 108.712,-18.462 108.712,-13.297 ; 124.511,-28.956 124.511,-23.804
  text "COMPONENTS MARKED 'DNP' SHOULD NOT BE POPULATED." at 29.299,-8.09 h1.52
  text "ASSEMBLY VARIANT:" at 29.286,-11.024 h1.52
  text ".VariantName" at 55.601,-11.024 h1.52
  text "PCB VIEWED FROM TOP SIDE" at -5.804,-16.654 h1.52
  text "BOARD #:" at 57.099,-16.654 h1.52
  text ".PRJ_Number" at 70.955,-16.654 h1.52
  text "REV:" at 92.405,-16.654 h1.52
  text ".PCB_Rev" at 99.809,-16.654 h1.52
  text "SVN REV:" at 113.69,-16.654 h1.52
  text ".VersionControl_RevNumber" at 126.543,-16.654 h1.52
  text "TID #:" at 57.099,-21.819 h1.52
  text ".TID" at 70.955,-21.819 h1.52
  text "PLOT NAME =" at -5.804,-27.034 h1.52
  text ".plot_File_Name" at 14.656,-27.034 h1.52
  text "GENERATED    :" at 57.15,-27.034 h1.52
  text ".Print_Date" at 79.235,-27.034 h1.52
  text ".Print_Time" at 97.752,-27.034 h1.52
  text "TEXAS INSTRUMENTS" at 129.87,-27.034 h1.52
M6 Assembly Bottom:
  lines w0.254: -7.429,-18.474 160.261,-18.474 ; -7.379,-23.639 160.261,-23.639 ; 28.334,-28.969 28.334,-23.817 ; 44.133,-18.474 44.133,-13.31 ; 65.468,-18.474 65.468,-13.31 ; 97.65,-28.804 97.65,-13.31 ; 120.231,-28.804 160.249,-28.804 160.249,-13.31 -7.429,-13.31 -7.429,-28.804 58.534,-28.804 160.261,-28.804 160.261,-13.31
  text "COMPONENTS MARKED 'DNP' SHOULD NOT BE POPULATED." at 154.991,-8.077 h1.52
  text ".VariantName" at 128.473,-11.024 h1.52
  text "ASSEMBLY VARIANT:" at 154.864,-11.024 h1.52
  text ".VersionControl_RevNumber" at 26.302,-16.667 h1.52
  text "SVN REV:" at 39.154,-16.667 h1.52
  text ".PCB_Rev" at 53.035,-16.667 h1.52
  text "REV:" at 60.439,-16.667 h1.52
  text ".PRJ_Number" at 81.89,-16.667 h1.52
  text "BOARD #:" at 95.745,-16.667 h1.52
  text "PCB VIEWED FROM BOTTOM SIDE" at 158.648,-16.667 h1.52
  text ".TID" at 81.89,-21.831 h1.52
  text "TID #:" at 95.745,-21.831 h1.52
  text "TEXAS INSTRUMENTS" at 22.974,-27.047 h1.52
  text ".Print_Time" at 55.093,-27.047 h1.52
  text ".Print_Date" at 73.609,-27.047 h1.52
  text "GENERATED    :" at 95.694,-27.047 h1.52
  text ".plot_File_Name" at 138.189,-27.047 h1.52
  text "PLOT NAME =" at 158.648,-27.047 h1.52
M9 Title Sheet:
  drawing of 57 lines, arcs and shapes, not listed
  text "1" at 18.792,204.127 h1.78
  text "2" at 82.182,204.127 h1.78
  text "3" at 145.411,204.127 h1.78
  text "4" at 209.08,204.127 h1.78
  text "5" at 272.555,204.127 h1.78
  text "6" at 336.182,204.127 h1.78
  text "A" at -10.579,175.095 h1.78
  text "A" at 365.341,175.095 h1.78
  text "B" at -10.579,114.643 h1.78
  text "B" at 365.341,114.643 h1.78
  text "C" at -10.579,54.318 h1.78
  text "C" at 365.341,54.318 h1.78
  text "PROJECT TITLE:" at 288.125,7.048 h1.14
  text ".PRJ_Title" at 289.395,3.662 h1.78
  text "DESIGNED FOR:" at 288.125,-0.597 h1.14
  text ".PRJ_Customer" at 289.395,-4.153 h1.78
  text "D" at -10.579,-5.88 h1.78
  text "D" at 365.341,-5.88 h1.78
  text "FILE NAME:" at 288.125,-8.217 h1.14
  text ".PCB_File_Name_No_Path" at 289.395,-11.265 h1.78
  text "Texas Instruments (TI) and/or its licensors do not warrant the accuracy or completeness of this specification" at 161.9,-15.376 h1.14
  text "ENGINEER:" at 288.125,-15.583 h1.14
  text "LAYOUT BY:" at 326.352,-15.583 h1.14
  text "or any information contained therein. TI and/or its licensors do not warrant that this design will meet" at 160.757,-18.237 h1.14
  text ".PRJ_Engineer" at 289.395,-19.52 h1.78
  text ".PCB_Layout" at 327.635,-19.52 h1.78
  text "the specifications, will be suitable for your application or fit for any particular purpose, or will operate in" at 160.757,-21.099 h1.14
  text ".Layer_Name" at 14.656,-21.806 h1.52
  text "ALTIUM DESIGNER VERSION:" at 326.352,-23.457 h1.14
  text "an implementation. TI and/or its licensors do not warrant that the design is production worthy. You should" at 160.757,-23.961 h1.14
  text "completely validate and test your design implementation to confirm the system functionality for your application." at 161.9,-26.822 h1.14
  text ".print_Scale" at 289.395,-26.843 h1.78
  text ".Application_BuildNumber" at 327.635,-26.843 h1.78
  text "1" at 18.792,-32.093 h1.78
  text "2" at 82.182,-32.093 h1.78
  text "3" at 145.411,-32.093 h1.78
  text "4" at 209.08,-32.093 h1.78
  text "5" at 272.555,-32.093 h1.78
  text "6" at 336.182,-32.093 h1.78
M10 Fab Notes:
  drawing of 189 lines, arcs and shapes, not listed
  text "DESIGN INFORMATION" at 314.503,161.447 h1.52
  text "MIN. TRACK WIDTH:" at 298.131,158.091 h1.52
  text "8" at 325.976,158.091 h1.52
  text "MIL" at 329.907,158.091 h1.52
  text "7.874" at 321.75,155 h1.52
  text "MIN. CLEARANCE:" at 298.131,154.938 h1.52
  text "MIL" at 329.907,154.938 h1.52
  text "MIN. VIA PAD SIZE:" at 298.131,151.785 h1.52
  text "24" at 325.214,151.785 h1.52
  text "MIL" at 329.907,151.785 h1.52
  text "0.05mm (2MIL)" at 315.784,148.486 h1.52
  text "MINIMUM ANNULAR RING" at 289.769,148.277 h1.52
  text "EXTERNAL" at 333.768,148.277 h1.52
  text "PER" at 294.849,145.48 h1.52
  text "IPC-D-275 CLASS 2 LEVEL C" at 300.437,145.48 h1.52
  text "MIL, HOLES" at 338.238,142.928 h1.52
  text "+/-" at 328.27,142.709 h1.52
  text "+/-" at 349.961,142.709 h1.52
  text "REGISTRATION TOLERANCES:" at 289.769,142.682 h1.52
  text "METAL" at 320.243,142.682 h1.52
  text "5" at 334.879,142.683 h1.52
  text "3" at 356.037,142.683 h1.52
  text "MIL" at 358.99,142.682 h1.52
  text "HOLE SIZE TOLERANCE (UNLESS OTHERWISE SPECIFIED):" at 289.769,140.185 h1.52
  text "+/-" at 349.961,140.112 h1.52
  text "3" at 356.037,140.085 h1.52
  text "MIL" at 358.99,140.085 h1.52
  text "MATERIAL:" at 287.87,136.589 h1.52
  text "FR-4 High Tg" at 312.926,133.324 h1.52
  text "X" at 309.257,133.122 h1.52
  text "FR-4" at 298.563,133.007 h1.52
  text "OTHER" at 336.358,133.007 h1.52
  text "62 MIL (1.6mm) +/-10%" at 306.694,129.374 h1.52
  text "X" at 303.643,129.312 h1.52
  text "THICKNESS:" at 289.769,129.165 h1.52
  text "OTHER" at 339.33,129.165 h1.52
  text "TOLERANCE:" at 289.769,125.652 h1.52
  text "X" at 311.314,125.652 h1.52
  text "ANSI IPC-6012 TYPE 3 CLASS 2" at 315.836,125.652 h1.52
  text "OTHER +/-" at 315.835,121.989 h1.52
  text "BOW & TWIST:" at 289.769,118.302 h1.52
  text "X" at 311.314,118.302 h1.52
  text "ANSI IPC-6012 TYPE 3 CLASS 2" at 315.836,118.302 h1.52
  text "OTHER +/-" at 315.835,114.576 h1.52
  text "DRILLING:" at 287.87,111.258 h1.52
  text "NC_DRILL FILES" at 332.599,108.586 h1.52
  text "REFERENCE:" at 289.769,108.486 h1.52
  text "X" at 306.463,108.484 h1.52
  text "AS SHOWN" at 310.984,108.486 h1.52
  text "X" at 329.348,108.486 h1.52
  text "OTHER" at 340.168,104.873 h1.52
  text "PTH COPPER THICKNESS:" at 289.761,104.783 h1.52
  text "X" at 318.697,104.783 h1.52
  text "20-30 um" at 321.948,104.783 h1.52
  text "BOARD FINISH:" at 287.87,101.034 h1.52
  text "SILKSCREEN:" at 291.812,98.237 h1.52
  text "X" at 316.14,98.237 h1.52
  text "TOP" at 319.112,98.237 h1.52
  text "X" at 329.094,98.237 h1.52
  text "BOTTOM" at 332.091,98.237 h1.52
  text "SILKSCREEN COLOR:" at 291.812,94.295 h1.52
  text "X" at 316.115,94.295 h1.52
  text "WHITE" at 319.112,94.295 h1.52
  text "OTHER" at 332.091,94.295 h1.52
  text "X" at 319.442,90.652 h1.52
  text "GREEN" at 322.439,90.652 h1.52
  text "OTHER" at 338.136,90.652 h1.52
  text "SOLDER RESIST COLOR:" at 291.812,90.477 h1.52
  text "X" at 319.442,86.734 h1.52
  text "MATTE" at 322.439,86.734 h1.52
  text "SEMI-GLOSS" at 338.125,86.717 h1.52
  text "IMMERSION GOLD (ENIG)" at 314.819,82.345 h1.52
  text "ENEPIG" at 348.793,82.162 h1.52
  text "SURFACE FINISH:" at 287.87,82.136 h1.52
  text "X" at 310.298,82.136 h1.52
  text "IMM. TIN/SILVER OR EQUIV" at 296.24,78.649 h1.52
  text "OTHER" at 332.599,78.549 h1.52
  text "ARRAY/PANEL:" at 287.87,74.602 h1.52
  text "CUT AND TRIM PER M1 BOARD OUTLINE" at 314.819,74.393 h1.52
  text "N.C. ROUTE" at 314.819,70.94 h1.52
  text "X" at 332.295,70.94 h1.52
  text "V. SCORE" at 336.816,70.94 h1.52
  text "CERTIFICATION:" at 287.87,67.66 h1.52
  text "MATERIALS AND WORKMANSHIP FOR ALL PCBS" at 306.285,67.66 h1.52
  text "TO MEET OR EXCEED THE REQUIREMENTS OF:" at 306.285,65.271 h1.52
  text "X" at 297.078,62.003 h1.52
  text "ANSI IPC-A-600F CLASS ->" at 300.329,62.003 h1.52
  text "X" at 342.188,62.003 h1.52
  text "2" at 344.982,62.003 h1.52
  text "1" at 336.981,61.965 h1.52
  text "3" at 353.973,61.965 h1.52
  text "X" at 317.702,58.252 h1.52
  text "RoHS" at 320.953,58.252 h1.52
  text "OTHER" at 337.321,58.252 h1.52
  text "PER ORDER" at 347.407,58.252 h1.52
  text "ALL BOARDS MUST MEET OR EXCEED UL94-V0 REQUIREMENTS." at 288.569,54.345 h1.52
  text "PCB MUST BEAR THE UL94V-0 UL REGISTERED MATERIAL ID NUMBER" at 288.569,51.397 h1.52
  text "ADDITIONAL REQUIREMENTS:" at 287.87,47.094 h1.52
  text "MICROSECTION:" at 289.769,44.373 h1.52
  text "YES" at 312.775,44.373 h1.52
  text "REQUIRED" at 334.657,40.707 h1.52
  text "BARE BOARD ELEC. TEST:" at 289.769,40.634 h1.52
  text "NONE" at 322.935,40.634 h1.52
  text "X" at 331.66,40.634 h1.52
  text "PER ORDER" at 349.693,40.634 h1.52
  text "XX MIL VIAS REQUIRE NON-CONDUCTIVE FILL AND PLANARIZE" at 294.04,35.428 h1.5
  text "XX MIL VIAS REQUIRE CONDUCTIVE FILL AND PLANARIZE" at 294.243,32.787 h1.52
  text "OUTER XX MIL TRACES REQUIRE 50 OHM SINGLE-ENDED IMPEDANCE" at 294.218,28.637 h1.47
  text "LAYER 2 & 3 (INNER LAYERS) XX MIL WIDE, XX MIL SPACE / TRACES REQUIRE 100 OHM DIFFERENTIAL IMPEDANCE" at 294.015,22.65 h1.52
  text ".Layer_Name" at 14.656,-21.806 h1.52
M11 Gerber Information:
  lines w0.254: -7.417,-23.626 160.223,-23.626 ; -7.417,-18.462 160.274,-18.462 ; -7.417,-13.297 -7.417,-28.791 94.31,-28.791 160.274,-28.791 160.274,-13.297 -7.404,-13.297 -7.404,-28.791 32.614,-28.791 ; 55.194,-28.791 55.194,-13.297 ; 87.376,-18.462 87.376,-13.297 ; 108.712,-18.462 108.712,-13.297 ; 124.511,-28.956 124.511,-23.804
  text "ALL ARTWORK VIEWED FROM TOP SIDE" at -5.804,-16.654 h1.52
  text "BOARD #:" at 57.099,-16.654 h1.52
  text ".PRJ_Number" at 70.955,-16.654 h1.52
  text "REV:" at 92.405,-16.654 h1.52
  text ".PCB_Rev" at 99.809,-16.654 h1.52
  text "SVN REV:" at 113.69,-16.654 h1.52
  text ".VersionControl_RevNumber" at 126.543,-16.654 h1.52
  text "LAYER NAME =" at -5.804,-21.806 h1.52
  text "TID #:" at 57.099,-21.819 h1.52
  text ".TID" at 70.955,-21.819 h1.52
  text "PLOT NAME =" at -5.804,-27.034 h1.52
  text ".plot_File_Name" at 14.656,-27.034 h1.52
  text "GENERATED    :" at 57.15,-27.034 h1.52
  text ".Print_Date" at 79.235,-27.034 h1.52
  text ".Print_Time" at 97.752,-27.034 h1.52
  text "TEXAS INSTRUMENTS" at 129.87,-27.034 h1.52
M12 Stackup:
  drawing of 295 lines, arcs and shapes, not listed
  text "Layer" at 249.469,200.023 h1.52
  text "Name" at 259.88,200.023 h1.52
  text "Material" at 283.496,200.023 h1.52
  text "Thickness" at 305.334,200.023 h1.52
  text "Constant" at 321.84,200.023 h1.52
  text "Board Layer Stack" at 336.314,200.023 h1.52
  text "Top Overlay" at 259.88,196.975 h1.52
  text "Top Solder" at 259.88,193.927 h1.52
  text "Solder Resist" at 283.496,193.927 h1.52
  text "0.40mil" at 305.334,193.927 h1.52
  text "3.5" at 321.84,193.927 h1.52
  text "1" at 249.469,190.879 h1.52
  text "Top Layer" at 259.88,190.879 h1.52
  text "1.40mil" at 305.334,190.879 h1.52
  text "Dielectric 1" at 259.88,187.831 h1.52
  text "PP-006" at 283.496,187.831 h1.52
  text "2.80mil" at 305.334,187.831 h1.52
  text "4.1" at 321.84,187.831 h1.52
  text "2" at 249.469,184.783 h1.52
  text "Layer 1" at 259.88,184.783 h1.52
  text "CF-004" at 283.496,184.783 h1.52
  text "1.38mil" at 305.334,184.783 h1.52
  text "Dielectric1" at 259.88,181.735 h1.52
  text "FR-4 High Tg" at 283.496,181.735 h1.52
  text "59.20mil" at 305.334,181.735 h1.52
  text "4.8" at 321.84,181.735 h1.52
  text "3" at 249.469,178.687 h1.52
  text "Layer 2" at 259.88,178.687 h1.52
  text "CF-004" at 283.496,178.687 h1.52
  text "1.38mil" at 305.334,178.687 h1.52
  text "Dielectric 2" at 259.88,175.639 h1.52
  text "PP-006" at 283.496,175.639 h1.52
  text "2.80mil" at 305.334,175.639 h1.52
  text "4.1" at 321.84,175.639 h1.52
  text "4" at 249.469,172.591 h1.52
  text "Bottom Layer" at 259.88,172.591 h1.52
  text "1.40mil" at 305.334,172.591 h1.52
  text "Bottom Solder" at 259.88,169.543 h1.52
  text "Solder Resist" at 283.496,169.543 h1.52
  text "0.40mil" at 305.334,169.543 h1.52
  text "3.5" at 321.84,169.543 h1.52
  text "Bottom Overlay" at 259.88,166.495 h1.52
  text ".Layer_Name" at 14.656,-21.806 h1.52
M13 Component Bodies Top:
  text ".Layer_Name" at 14.656,-21.806 h1.52
M14 Component Bodies Bottom:
  text ".Layer_Name" at 14.656,-21.806 h1.52
M15 Courtyards Top:
  text ".Layer_Name" at 14.656,-21.806 h1.52
M16 Courtyards Bottom:
  text ".Layer_Name" at 14.656,-21.806 h1.52
Drill Drawing:
  text ".Layer_Name" at 14.656,-21.806 h1.52
M17 Embedded Cavity:
  text ".Layer_Name" at 14.656,-21.806 h1.52
M18 Embedded Assembly:
  text ".Layer_Name" at 14.656,-21.806 h1.52
M19 Embedded Keepout:
  text ".Layer_Name" at 14.656,-21.806 h1.52

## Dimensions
0,-10.16 to 25.4,-10.16 on M2 Board Dimensions
0,127 to 209,0 on M2 Board Dimensions
209,0 to 0,127 on M2 Board Dimensions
